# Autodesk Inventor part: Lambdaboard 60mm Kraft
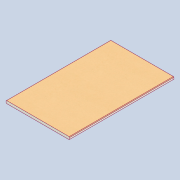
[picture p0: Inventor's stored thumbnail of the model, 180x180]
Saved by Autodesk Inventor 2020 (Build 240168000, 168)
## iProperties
Created: 2020-11
Part Number: Lambdaboard 60mm Kraft
Material: Polyisocyanurate
Document SubType Name: Modeling
Designer: Yolande
Density: 0.032 g/cm^3
Appearance: Pink
Author: Yolande
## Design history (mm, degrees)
sketch "Sketch1"
  geometry: L1 (10, 0)-(1210, 0); L2 (1220, 10)-(1220, 40); L3 (1210, 50)-(10, 50); L4 (0, 40)-(0, 10); A1 r 10 centre (10, 40) between (10, 50) and (0, 40); A2 r 10 centre (10, 10) between (0, 10) and (10, 0); A3 r 10 centre (1210, 40) between (1220, 40) and (1210, 50); A4 r 10 centre (1210, 10) between (1210, 0) and (1220, 10); 3 further points
  constraints: 8 end point, 8 point on circle, 8 tangent, 6 point on line, 4 centre point, 3 equal radius, 3 perpendicular, 1 horizontal
  dimensions: "d0" = 1220 distance of point (0, 0) point (1220, 0); "d1" = 50 distance of point (1220, 0) point (1220, 50); "d2" = 10 radius of A1
extrude "Extrusion1" new body sketch "Sketch1" distance "d3" = 2000; taper "d4" = 0 deg
body "Solid1"
